// Mitsubishi GX Works2 project: 实例练习(多点记录+位移)1111   PLC: FX3U/FX3UC

PROGRAM MAIN
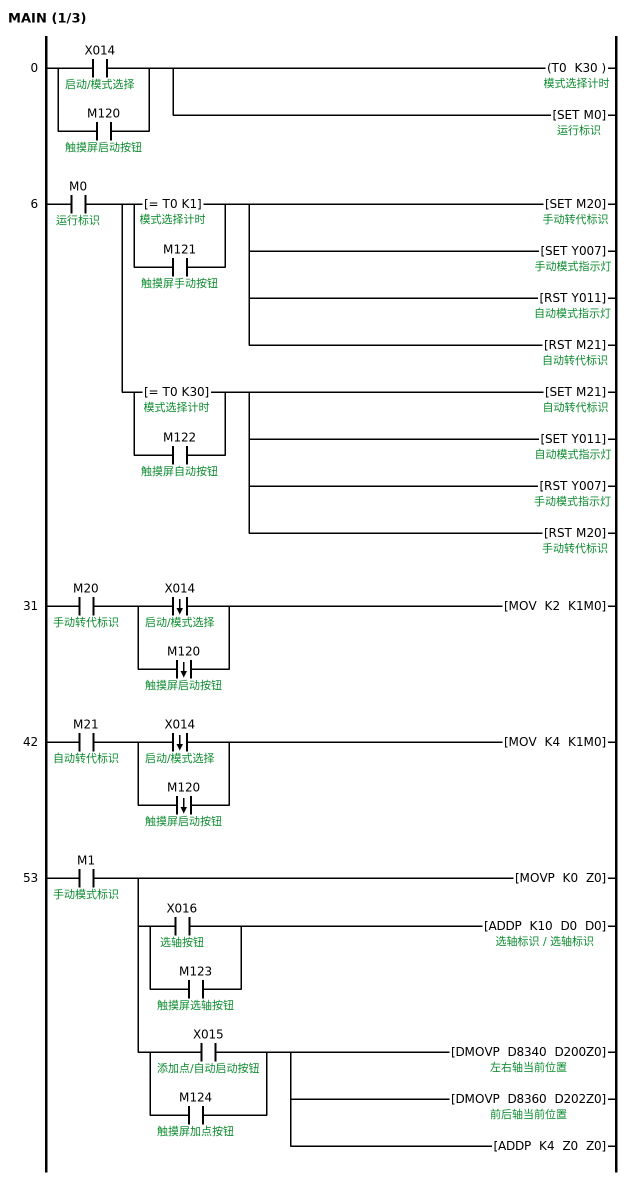
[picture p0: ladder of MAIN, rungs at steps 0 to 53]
0     LD      X014  ; 启动/模式选择
      OR      M120  ; 触摸屏启动按钮
      OUT     T0 K30  ; 模式选择计时
      SET     M0  ; 运行标识
6     LD      M0  ; 运行标识
      MPS
      LD=     T0 K1  ; 模式选择计时
      OR      M121  ; 触摸屏手动按钮
      ANB
      SET     M20  ; 手动转代标识
      SET     Y007  ; 手动模式指示灯
      RST     Y011  ; 自动模式指示灯
      RST     M21  ; 自动转代标识
      MPP
      LD=     T0 K30  ; 模式选择计时
      OR      M122  ; 触摸屏自动按钮
      ANB
      SET     M21  ; 自动转代标识
      SET     Y011  ; 自动模式指示灯
      RST     Y007  ; 手动模式指示灯
      RST     M20  ; 手动转代标识
31    LD      M20  ; 手动转代标识
      LDF     X014  ; 启动/模式选择
      ORF     M120  ; 触摸屏启动按钮
      ANB
      MOV     K2 K1M0
42    LD      M21  ; 自动转代标识
      LDF     X014  ; 启动/模式选择
      ORF     M120  ; 触摸屏启动按钮
      ANB
      MOV     K4 K1M0
53    LD      M1  ; 手动模式标识
      MOVP    K0 Z0
      MPS
      LD      X016  ; 选轴按钮
      OR      M123  ; 触摸屏选轴按钮
      ANB
      ADDP    K10 D0 D0  ; 选轴标识
      MPP
      LD      X015  ; 添加点/自动启动按钮
      OR      M124  ; 触摸屏加点按钮
      ANB
      DMOVP   D8340 D200Z0  ; 左右轴当前位置
      DMOVP   D8360 D202Z0  ; 前后轴当前位置
      ADDP    K4 Z0 Z0
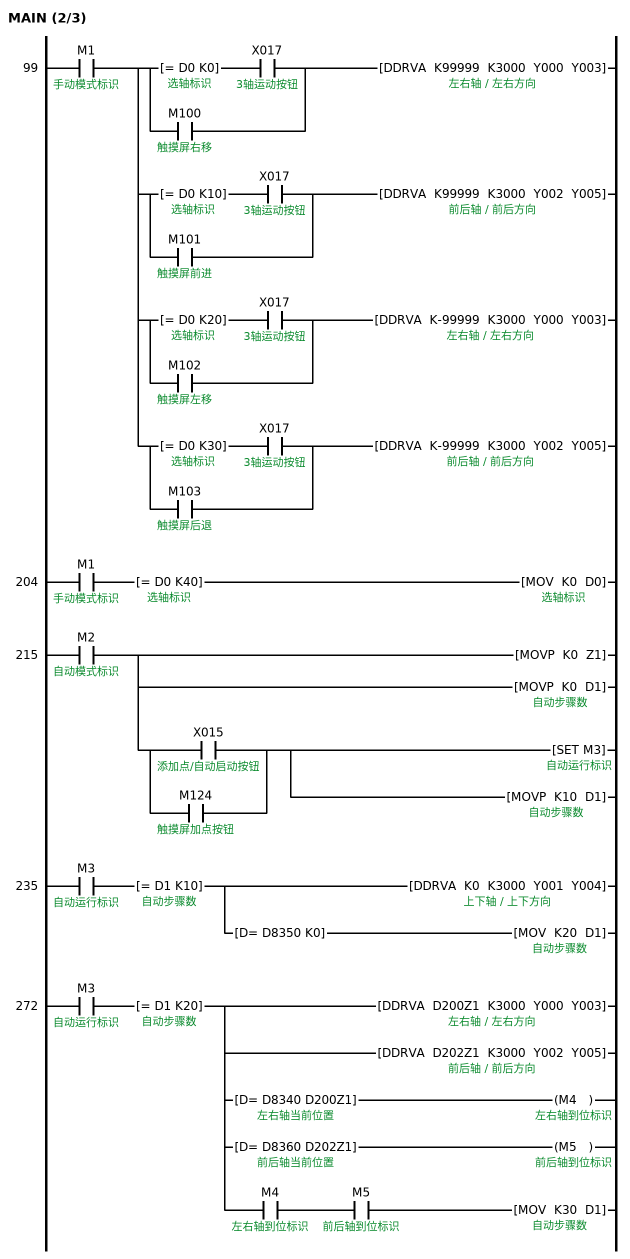
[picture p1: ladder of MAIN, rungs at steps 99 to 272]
99    LD      M1  ; 手动模式标识
      MPS
      LD=     D0 K0  ; 选轴标识
      AND     X017  ; 3轴运动按钮
      OR      M100  ; 触摸屏右移
      ANB
      DDRVA   K99999 K3000 Y000 Y003  ; 左右轴 / 左右方向
        [note] Y0为+右行
      MRD
      LD=     D0 K10  ; 选轴标识
      AND     X017  ; 3轴运动按钮
      OR      M101  ; 触摸屏前进
      ANB
      DDRVA   K99999 K3000 Y002 Y005  ; 前后轴 / 前后方向
        [note] Y2为+前行
      MRD
      LD=     D0 K20  ; 选轴标识
      AND     X017  ; 3轴运动按钮
      OR      M102  ; 触摸屏左移
      ANB
      DDRVA   K-99999 K3000 Y000 Y003
        [note] Y0为-左行
      MPP
      LD=     D0 K30  ; 选轴标识
      AND     X017  ; 3轴运动按钮
      OR      M103  ; 触摸屏后退
      ANB
      DDRVA   K-99999 K3000 Y002 Y005
        [note] Y0为-后行
204   LD      M1  ; 手动模式标识
      AND=    D0 K40  ; 选轴标识
      MOV     K0 D0
215   LD      M2  ; 自动模式标识
      MOVP    K0 Z1
      MOVP    K0 D1  ; 自动步骤数
      LD      X015  ; 添加点/自动启动按钮
      OR      M124  ; 触摸屏加点按钮
      ANB
      SET     M3  ; 自动运行标识
      MOVP    K10 D1
235   LD      M3  ; 自动运行标识
      AND=    D1 K10  ; 自动步骤数
      DDRVA   K0 K3000 Y001 Y004  ; 上下轴 / 上下方向
      ANDD=   D8350 K0
      MOV     K20 D1
272   LD      M3  ; 自动运行标识
      AND=    D1 K20  ; 自动步骤数
      DDRVA   D200Z1 K3000 Y000 Y003
      DDRVA   D202Z1 K3000 Y002 Y005
      MPS
      ANDD=   D8340 D200Z1  ; 左右轴当前位置
      OUT     M4  ; 左右轴到位标识
      MRD
      ANDD=   D8360 D202Z1  ; 前后轴当前位置
      OUT     M5  ; 前后轴到位标识
      MPP
      AND     M4  ; 左右轴到位标识
      AND     M5  ; 前后轴到位标识
      MOV     K30 D1
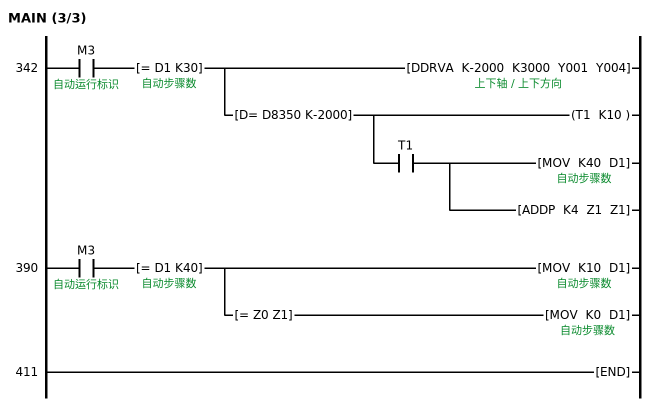
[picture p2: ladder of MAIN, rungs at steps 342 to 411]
342   LD      M3  ; 自动运行标识
      AND=    D1 K30  ; 自动步骤数
      DDRVA   K-2000 K3000 Y001 Y004
      ANDD=   D8350 K-2000
      OUT     T1 K10
      AND     T1
      MOV     K40 D1
      ADDP    K4 Z1 Z1
390   LD      M3  ; 自动运行标识
      AND=    D1 K40  ; 自动步骤数
      MOV     K10 D1
      AND=    Z0 Z1
      MOV     K0 D1
411   END
END_PROGRAM

// device comments not shown above
D200  ; 左右轴预存位置
D202  ; 前后轴预存位置
